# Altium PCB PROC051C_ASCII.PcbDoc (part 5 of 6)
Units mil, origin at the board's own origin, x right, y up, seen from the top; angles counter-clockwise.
Board outline 3304.03 x 2647.77 mil, 6 copper layers (TOP, L2, L3, L4, L5, BOTTOM), stack 55.54 mil thick; 370 components, 273 nets, 1273 pads, 1381 vias.
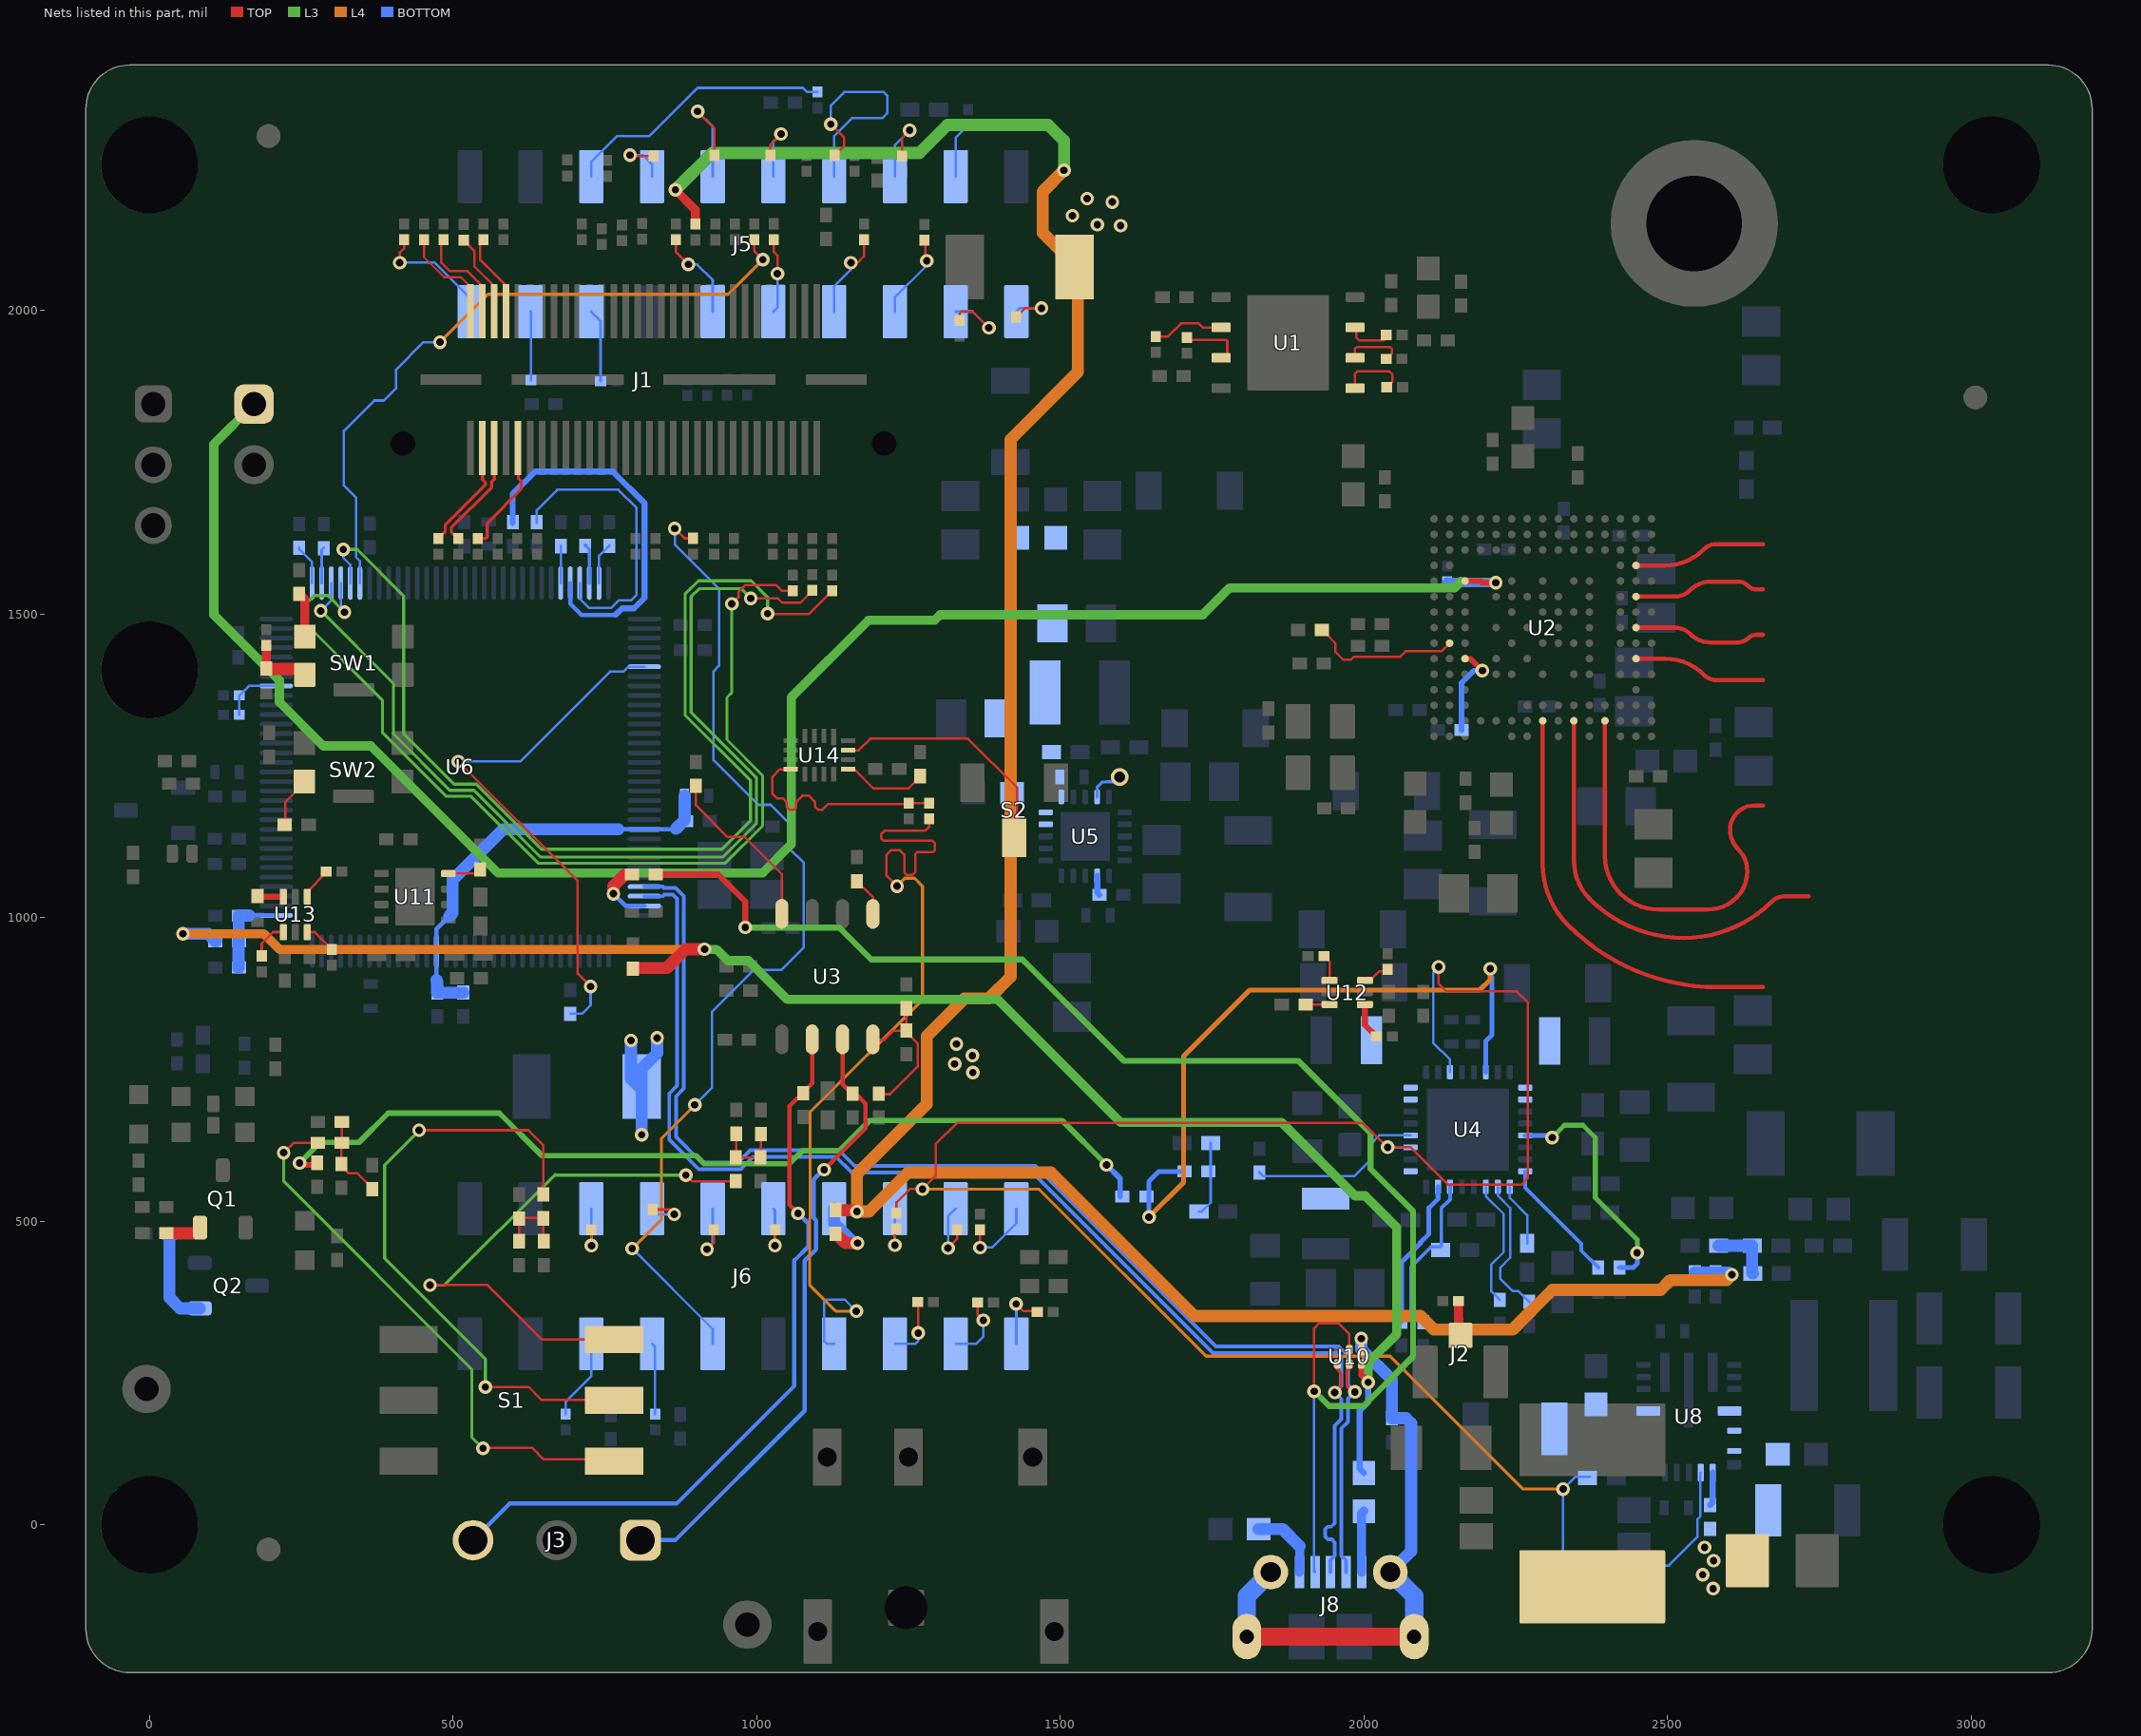
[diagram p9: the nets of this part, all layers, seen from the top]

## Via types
v1: diameter 22.4, hole 12.2, TOP to BOTTOM, tented both sides, 811 vias
v2: diameter 15.74, hole 5.9, TOP to L2, tented both sides, 528 vias
v3: diameter 19.68, hole 7.87, TOP to BOTTOM, 23 vias
v4: diameter 19.68, hole 7.87, TOP to BOTTOM, tented both sides, 7 vias
v5: diameter 22.4, hole 12.1, TOP to BOTTOM, tented both sides, 7 vias
v6: diameter 16, hole 8, TOP to BOTTOM, tented both sides, 4 vias
v7: diameter 15.74, hole 5.9, TOP to L2, tented top, 1 vias

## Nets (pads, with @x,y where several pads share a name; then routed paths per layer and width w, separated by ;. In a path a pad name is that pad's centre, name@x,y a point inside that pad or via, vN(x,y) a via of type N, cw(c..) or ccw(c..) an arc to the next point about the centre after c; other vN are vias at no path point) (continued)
NetJ1_52: J1.52 R50.1 | length 187.2
  TOP w5.2: R50.1@540.75,1624.71 553.36,1624.71 556,1627.35 556,1649.94 611.8,1705.74 611.8,1719.71 607.36,1724.15 J1.52@607.36,1773.27
NetJ1_53: J1.53 R22.2 | length 137.5
  TOP w4: R22.2@550.11,2116.73 544.7,2111.32 544.7,2083.31 587.67,2040.34 J1.53@587.67,1999.25
NetJ1_55: J1.55 R33.2 | length 138
  TOP w4: R33.2@517.39,2116.29 535,2098.68 535,2073 567.99,2040.01 J1.55@567.99,1999.25
NetJ1_56: J1.56 R49.1 | length 182.6
  TOP w5.2: R49.1@508.25,1624.71 497.03,1635.93 497.03,1642.53 563.2,1708.7 563.2,1717.88 567.99,1722.67 J1.56@567.99,1773.27
NetJ1_57: J1.57 R21.2 | length 164.6
  TOP w4: R21.2@484.35,2116.73 480,2112.38 480,2080.01 495.01,2065 524,2065 548.3,2040.7 J1.57@548.3,1999.25
NetJ1_58: J1.58 R48.1 | length 182.6
  TOP w5.2: R48.1@475.61,1624.71 486.83,1635.93 486.83,1646.76 553,1712.93 553,1717.35 548.3,1722.05 J1.58@548.3,1773.27
NetJ1_59: J1.59 R20.2 | length 165.6
  TOP w4: R20.2@452.11,2116.73 452.11,2087.89 485,2055 513.01,2055 528.62,2039.39 J1.59@528.62,1999.25
NetJ2_1: J2.1 R111.2 | length 58.2
  TOP w15: R111.2@2155.99,369 2155.99,340.01 2156,315.04 J2.1@2159,312.04
NetJ3_1: J3.1 R85.2 U3.7 | length 1034
  TOP w7: v1(1111,585) 1179.1,653.1 1179.1,693.8 1163.2,709.7 1158,709.7 1157,709.7 1141.31,725.39 U3.7@1141.31,798.65
  BOTTOM w7: J3.1@808.4,-25.28 865.72,-25.28 1079,188 1079,435 1097.7,453.7 1097.7,501.68 1094,505.38 1094,569 1110,585 v1(1111,585)
NetJ3_3: J3.3 R87.1 U3.6 | length 1242
  TOP w7: v1(1068,513) 1054,527 1054,690 1075.89,711.89 1091.31,727.31 U3.6@1091.31,798.65
  BOTTOM w7: J3.3@532.8,-25.28 593.08,35 868,35 1062,229 1062,435.71 1085,458.71 1085,496 v1(1068,513)
NetJ5_1: J5.1 R19.2 | length 203
  TOP w4: v1(412,2079) 412,2095 419.25,2102.25 R19.2@419.25,2116.73
  BOTTOM w4: v1(412,2079) 469.5,2079 527.5,2021 J5.1@527.5,1998.28
NetJ5_3: J5.3 R24.2 | length 112.9
  BOTTOM w4: J5.3@627.5,1998.28 628.11,1997.67 R24.2@628.11,1885.6
NetJ5_5: J5.5 R25.2 | length 120.8
  BOTTOM w4: J5.5@727.5,1998.28 742.81,1982.97 R25.2@742.81,1883.8
NetJ5_6: J5.6 R1.1 | length 449.8
  BOTTOM w4: J5.6@727.5,2220.72 727.5,2244.5 770.5,2287.5 823.1,2287.5 902.5,2366.9 1076,2366.9 1082.91,2359.99 R1.1@1100,2359.99
NetJ5_8: J5.8 R9.1 | length 102
  TOP w4: v1(791.2,2256.2) 792.69,2254.71 R9.1@829.75,2254.71
  BOTTOM w4: v1(791.2,2256.2) 812.2,2256.2 827.5,2240.9 J5.8@827.5,2220.72
NetJ5_9: J5.9 R26.2 | length 152.1
  TOP w4: R26.2@866.7,2116.61 866.7,2096.7 v1(887.4,2076)
  BOTTOM w4: v1(887.4,2076) 902,2076 927.5,2050.5 J5.9@927.5,1998.28
NetJ5_10: J5.10 R2.1 | length 201.2
  TOP w4: v1(902.66,2328) 930.05,2300.61 R2.1@930.05,2255.71
  BOTTOM w4: v1(902.66,2328) 927.5,2303.16 J5.10@927.5,2220.72
NetJ5_11: J5.11 R18.2 | length 124
  TOP w4: R18.2@1028.21,2117.08 1028.21,2096.79 1034.1,2090.9 v1(1034.1,2061)
  BOTTOM w4: J5.11@1027.5,1998.28 1034.1,2004.88 v1(1034.1,2061)
NetJ5_12: J5.12 R4.1 | length 118
  TOP w4: R4.1@1022.55,2255.71 1022.55,2273.55 v1(1040,2291)
  BOTTOM w4: J5.12@1027.5,2220.72 1027.5,2278.5 v1(1040,2291)
NetJ5_13: J5.13 R31.2 | length 145.3
  TOP w4: v1(1155,2079) 1166,2079 1176.75,2089.75 R31.2@1176.75,2116.73
  BOTTOM w4: J5.13@1127.5,1998.28 1127.5,2040.5 1155,2068 v1(1155,2079)
NetJ5_14: J5.14 R6.1 | length 401.4
  TOP w4: v1(1122,2307) 1144,2285 1144,2271.66 R6.1@1128.05,2255.71
  BOTTOM w4: v1(1122,2307) 1122,2338 1144,2360 1209,2360 1215,2354 1215,2325 1207,2317 1157,2317 1127.5,2287.5 J5.14@1127.5,2220.72
NetJ5_15: J5.15 R32.2 | length 141.2
  TOP w4: R32.2@1277.55,2116.73 1278,2116.28 1278,2116.01 1278,2084 v1(1280,2082)
  BOTTOM w4: J5.15@1227.5,1998.28 1227.5,2021.5 1280,2074 v1(1280,2082)
NetJ5_16: J5.16 R10.1 | length 134
  TOP w4: R10.1@1239.25,2254.71 1239.25,2284.25 v1(1252,2297)
  BOTTOM w4: J5.16@1227.5,2220.72 1227.5,2272.5 v1(1252,2297)
NetJ5_17: J5.17 R35.2 | length 137.7
  TOP w4: R35.2@1334,1983.99 1334,1995 1337.5,1998.5 1355.59,1998.5 v1(1382.33,1971.76)
  BOTTOM w4: J5.17@1327.5,1998.28 1355.81,1998.28 v1(1382.33,1971.76)
NetJ5_18: J5.18 R8.1 | length 92.8
  BOTTOM w4: J5.18@1327.5,2220.72 1327.5,2284.51 R8.1@1348,2305.01
NetJ5_19: J5.19 R36.2 | length 91.5
  TOP w4: R36.2@1427.25,1989.71 1441.54,2004 v1(1469,2004)
  BOTTOM w4: J5.19@1427.5,1998.28 1433.22,2004 v1(1469,2004)
NetJ6_5: J6.5 R169.2 | length 133.6
  BOTTOM w4: R169.2@685.13,182.27 685.13,202.33 727.5,244.7 J6.5@727.5,298.28
NetJ6_6: J6.6 R104.1 | length 87.1
  TOP w4: v1(727.75,460) R104.1@727.75,486.29
  BOTTOM w4: J6.6@727.5,520.72 727.5,460.25 v1(727.75,460)
NetJ6_7: J6.7 R166.2 | length 118.2
  BOTTOM w4: J6.7@827.5,298.28 832.75,293.03 R166.2@832.75,182.27
NetJ6_8: J6.8 R94.1 | length 79.3
  TOP w4: R94.1@828.25,519.29 856.21,519.29 v1(864,511.5)
  BOTTOM w4: J6.8@827.5,520.72 836.72,511.5 v1(864,511.5)
NetJ6_9: J6.9 R165.2 | length 1685.6
  TOP w4: v1(865,1641) 881.01,1624.99 R165.2@895,1624.99
  L4 w5: v1(795,455) 843.13,503.13 843.13,636.71 897.9,691.48 v1(897.9,691.7)
  BOTTOM w4: v1(795,455) 927.5,322.5 J6.9@927.5,298.28 ; v1(865,1641) 865,1615 938,1542 938,1415 928.8,1405.8 928.8,1259.48 1002.28,1186 1023,1186 1056,1153 1056,1111.72 1065.52,1102.2 1065.95,1102.2 1077.5,1090.66 1077.5,951.5 1040,914 995,914 926,845 926,719.8 v1(897.9,691.7)
NetJ6_10: J6.10 R105.1 | length 108
  TOP w4: v1(918,453.9) 929.75,465.65 R105.1@929.75,486.29
  BOTTOM w4: v1(918,453.9) 927.5,463.4 J6.10@927.5,520.72
NetJ6_12: J6.12 R106.1 | length 88.1
  TOP w4: v1(1030,460) 1030.25,460.25 R106.1@1030.25,486.29
  BOTTOM w4: J6.12@1027.5,520.72 1030,518.22 v1(1030,460)
NetJ6_13: J6.13 R76.2 | length 1443.2
  TOP w4: v1(1231,1052) 1213.64,1069.36 1213.64,1103.64 1221,1111 1236.1,1111 1243,1104.1 1243,1075.1 1247.6,1070.5 1256.1,1070.5 1261.5,1075.9 1261.5,1105 1265,1108.5 1290.5,1108.5 1293,1111 1293,1123 1288.87,1127.13 1208.6,1127.13 1204.6,1131.13 1204.6,1137.29 1210.44,1143.13 1277.13,1143.13 1284,1150 R76.2@1284,1163.01
  L4 w5: v1(1164,352) 1130,352 1087.3,394.7 1087.3,504.44 1087.7,504.84 1087.7,679.7 1273,865 1273,1052 1260,1065 1244,1065 v1(1231,1052)
  BOTTOM w4: J6.13@1127.5,298.28 1115,298.28 1111,302.28 1111,367 1115,371 1145,371 v1(1164,352)
NetJ6_14: J6.14 R107.1 | length 119.2
  TOP w20: R107.1@1129.75,480.38 1130.14,479.99 1146.13,464 v1(1166,464)
  BOTTOM w20: J6.14@1127.5,520.72 1127.5,496.5 1160,464 v1(1166,464)
NetJ6_15: J6.15 R164.2 | length 104.9
  TOP w4: R164.2@1265.01,367 1266,366.01 v1(1266,316)
  BOTTOM w4: J6.15@1227.5,298.28 1261.28,298.28 1266,303 v1(1266,316)
NetJ6_16: J6.16 R102.1 | length 88.1
  TOP w4: v1(1227.5,460.5) 1227.5,484.54 R102.1@1230.25,487.29
  BOTTOM w4: v1(1227.5,460.5) J6.16@1227.5,520.72
NetJ6_17: J6.17 R163.2 | length 110.2
  TOP w4: R163.2@1364.01,366 1364.02,345.98 v1(1373,337)
  BOTTOM w4: J6.17@1327.5,298.28 1361.44,298.28 1373,309.84 v1(1373,337)
NetJ6_18: J6.18 R108.1 | length 106.3
  TOP w4: v1(1315,456) 1330.35,471.35 R108.1@1330.35,486.09
  BOTTOM w4: v1(1315,456) 1315,508.22 J6.18@1327.5,520.72
NetJ6_19: J6.19 R162.2 | length 107.6
  TOP w4: v1(1427,364) 1439,352 1458.01,352 1459.51,353.5 R162.2@1462.01,356
  BOTTOM w4: v1(1427,364) 1427.5,363.5 J6.19@1427.5,298.28
NetJ6_20: J6.20 R109.1 | length 129.5
  TOP w4: v1(1367.85,456.8) R109.1@1367.85,486.09
  BOTTOM w4: v1(1367.85,456.8) 1387.61,456.8 1427.5,496.69 J6.20@1427.5,520.72
NetJ8_1: J8.1 R161.1 | length 101.9
  BOTTOM w15: J8.1@1996.18,-77.86 1996.18,18.68 R161.1@2000,22.5
NetJ8_5: J8.5 R175.2 | length 122
  BOTTOM w15: J8.5@1893.82,-77.86 1894,-77.68 1894,-35
  BOTTOM w20: R175.2@1826.5,-7 1866,-7 1894,-35
NetJ8_6: J8.6 J8.9 J8.10 J8.11 R174.2 U10.1 | length 987.2
  TOP w10: U10.1@1995.69,287.59 v1(1995.69,307)
  TOP w30: J8.9@1807.2,-184.16 J8.6@2082.8,-184.16
  BOTTOM w20: v1(1995.69,307) 1995.69,289.31 2046,239 R174.2@2046,175.69 2069.31,175.69 2078,167 2078,-43.29 J8.11@2043.43,-77.86
  BOTTOM w30: J8.9@1807.2,-184.16 1807.2,-117.23 J8.10@1846.57,-77.86 ; J8.11@2043.43,-77.86 2082.8,-117.23 J8.6@2082.8,-184.16
NetL2_1: L2.1 U4.25 U4.26
NetL3_1: L3.1 U4.15 U4.16
NetL4_2: L4.2 U4.9
NetQ1_1: Q1.1 R116.2 | length 67.6
  TOP w20: R116.2@26.68,480.33 R116.2@27.47,480.33 83.18,480.33 Q1.1@83.18,489.51 Q1.1@83.18,491.47
NetQ2_1: Q2.1 R160.2 | length 163.1
  BOTTOM w20: R160.2@32.69,480 32.69,374.31 50.4,356.6 Q2.1@82.76,356.6
NetR3_1: R3.1 U12.3 | length 40.2
  TOP w4: R3.1@1903.2,857.1 1903.31,857.21 1903.99,857.21 U12.3@1943.37,857.22
NetR5_2: R5.2 U12.1 | length 44.3
  TOP w4: R5.2@1933.99,937 1943.37,927.63 U12.1@1943.37,896.59
NetR11_2: R11.2 U3.1 | length 64.9
  TOP w4: R11.2@1165,1060.31 1191.31,1034 U3.1@1191.31,1006.33
NetR12_2: R12.2 U3.4 | length 285.1
  TOP w4: R12.2@900,1217.31 900,1185 952,1133 980.31,1133 1041.31,1072 U3.4@1041.31,1007.31
NetR39_2: R39.2 U1.2 | length 119.7
  TOP w4: R39.2@1656.9,1957.49 1677.49,1957.49 1699,1979 1727.76,1979 1734.58,1972.18 U1.2@1764.89,1972.18
NetR40_1: R40.1 U1.7 | length 69.4
  TOP w4: U1.7@1987.33,1972.18 1987.33,1955.67 1992,1951 2032.84,1951 R40.1@2036.69,1954.85
NetR42_2: R42.2 U1.3 | length 107.1
  TOP w4: R42.2@1708.5,1955.79 1712.29,1952 1773,1952 1775,1950 1775,1925 1772.18,1922.18 U1.3@1764.89,1922.18 U1.3@1762.93,1922.18
NetR44_1: R44.1 U1.6 | length 98.7
  TOP w4: U1.6@1985.37,1922.18 1985.37,1937.37 1988,1940 2043,1940 2046,1937 2046,1929.66 R44.1@2036.69,1920.35
NetR45_1: R45.1 U1.5 | length 114.4
  TOP w4: U1.5@1985.37,1872.18 1985.37,1896.37 1989,1900 2042,1900 2047,1895 2047,1883.16 R45.1@2037.69,1873.85
NetR47_1: R47.1 U2.G14 | length 247.1
  TOP w4: R47.1@1931.68,1469 1936,1469 1953,1452 1953,1437.78 1965.66,1425.11 1978.67,1425.11 1983.56,1430 2060,1430 2069.02,1439.02 2127.72,1439.02 U2.G14@2141.01,1452.31
NetR68_1: R68.1 SW1.4 | length 69.3
  TOP w15: R68.1@246.04,1534.25 246.43,1533.86 255.94,1524.35 SW1.4@255.94,1469.02
NetR72_1: R72.1 R73.2 SW1.2 | length 104.1
  TOP w15: R73.2@192.05,1409.82 192.44,1410.21 192.5,1410.27 192.5,1410.61 R72.1@192.5,1448.26
  TOP w20: R73.2@192.05,1409.82 252.14,1409.82 SW1.2@255.94,1406.02
NetR79_2: R79.2 SW2.2 | length 90.4
  TOP w4: R79.2@223.35,1153.14 223.35,1190.35 252.04,1219.04 252.04,1224.5 252.04,1227.45 SW2.2@254.99,1230.4
NetR81_1: R81.1 U2.F13 | length 157
  TOP w9: U2.F13@2166.6,1426.72 2175.28,1426.72 v1(2195,1407)
  BOTTOM w9: R81.1@2160.68,1309 2160.68,1386.68 2181,1407 v1(2195,1407)
NetR82_2: R82.2 U8.18 | length 55.3
  BOTTOM w10: R82.2@2570,32.69 2574.37,37.06 U8.18@2574.37,86.19
NetR86_1: R86.1 R177.2 R178.1 U3.8 | length 248.6
  TOP w4: U3.8@1191.31,798.65 1210.11,798.65 1225.06,813.6 R86.1@1246.3,813.6 ; R178.1@1200.8,709.5 1219.7,709.5 1265,754.8 1265,793 1246.3,811.7 R86.1@1246.3,813.6 ; R177.2@1246.5,851.45 R177.2@1246.5,850.66 1246.5,832 1246.3,831.8 R86.1@1246.3,814.39 R86.1@1246.3,813.6
NetR88_2: R88.2 R89.2 R92.1 R93.1 | length 120.8
  TOP w4: R88.2@966.12,644.95 R88.2@966.12,644.16 966.12,605.53 966.12,605.25 966.01,605.14 965.62,604.75 1005.82,604.75 1006.21,605.14 R93.1@1006.58,605.51 ; R93.1@1006.58,605.53 R89.2@1006.58,643.86 R89.2@1006.58,644.65
NetR92_2: R92.2 S1.3 | length 924.1
  TOP w4: v1(462,395) 556.29,395 646.29,305 S1.3@765.29,305 ; v1(883.4,576) 893.23,566.16 R92.2@965.62,566.16
  L3 w5: v1(462,395) 486,395 668,577 669,576 v1(883.4,576)
NetR95_1: R95.1 R96.2 R112.1 R113.2 | length 118.5
  TOP w4: R113.2@608.92,466.45 608.78,466.59 608.78,467.24 R96.2@608.78,504.56 608.78,505.35 648.52,505.35 648.82,505.65 R95.1@648.82,504.86 648.82,467.24 648.82,466.95 648.93,466.84 R112.1@649.32,466.45
NetR95_2: R95.2 S1.2 | length 1056.1
  TOP w4: v1(444,650) 624,650 648.82,625.18 R95.2@648.82,544.24 ; v1(553,227) 624.29,227 645.29,206 743.88,206 743.88,205 743.88,191.88 765.29,191.88 766.51,191.88 S1.2@772.46,197.83
  L3 w5: v1(444,650) 444,649.64 387.08,592.72 387.08,438.92 553,273 v1(553,227)
NetR98_2: R98.2 R99.1 R101.1 R114.2 | length 137.8
  TOP w4: R114.2@316.69,662 R99.1@316.68,629 316,628.32 R98.2@316,594.69 316,591 328,579 342.53,579 R101.1@367.28,554.25
NetR99_2: R99.2 S1.1 | length 911.6
  TOP w4: v1(221,613) 237,629 R99.2@277.31,629 ; v1(549,126) 550,127 630,127 649,108 762.29,108 S1.1@765.29,105
  L3 w5: v1(221,613) 221,566 530.72,256.28 530.72,144.28 v1(549,126)
NetR119_2: R119.2 U4.2 | length 232.5
  BOTTOM w4: U4.2@2222.2,555.06 U4.2@2220.48,556.78 2220.48,542.52 2241,522 2241,440.03 2224.3,423.33 2224.3,405.7 2244.6,385.4 2253.97,385.4 R119.2@2272,367.37
NetR120_2: R120.2 U5.12 | length 32.6
  BOTTOM w10: U5.12@1560.72,1069.04 1560.68,1041.63 R120.2@1564.31,1038
NetR121_2: R121.2 U4.3 | length 212.3
  BOTTOM w4: U4.3@2200.8,556.78 2200.8,541.2 2230,512 2230,449 2210,429 2210,384.69 R121.2@2224,370.69
NetR123_1: R123.1 U6.63 | length 69.2
  BOTTOM w4: U6.63@740.14,1551.19 740.14,1596.11 756.89,1612.86 R123.1@757.28,1613.25
NetR124_1: R124.1 U6.61 | length 488.4
  BOTTOM w4: R124.1@637.72,1650.75 R124.1@637.72,1651.53 637.72,1671.22 671.5,1705 772,1705 802,1675 802,1532 792.8,1522.8 772.8,1522.8 760.5,1510.5 723.5,1510.5 709,1525 709,1550.83 U6.61@708.64,1551.19
NetR125_2: R125.2 U6.59 | length 61.9
  BOTTOM w4: U6.59@677.14,1551.19 677.14,1612.16 677.14,1612.57 R125.2@677.52,1612.95
NetR126_1: R126.1 U6.62 | length 64.8
  BOTTOM w6: R126.1@717.68,1613.25 718.07,1612.86 724.39,1606.54 U6.62@724.39,1551.19
NetR127_1: R127.1 U6.60 | length 632.6
  BOTTOM w7: U6.60@692.89,1551.19 692.89,1517.05 710.94,1499 767.38,1499
  BOTTOM w10: R127.1@598.12,1650.75 R127.1@598.12,1651.53 598.12,1698.11 635.01,1735 763,1735 815,1683 815,1526.62 798.18,1509.8 778.18,1509.8 767.38,1499
NetR128_2: R128.2 U6.33 | length 67.5
  BOTTOM w4: R128.2@246.5,1609.95 R128.2@246.5,1609.16 246.5,1606.98 267.7,1585.78 U6.33@267.7,1551.19
NetR129_2: R129.2 U6.34 | length 59.9
  BOTTOM w4: U6.34@283.44,1551.19 283.44,1606.04 286.61,1609.21 R129.2@287,1609.6
NetR135_2: R135.2 R136.2 U6.25 | length 99.4
  BOTTOM w4: R136.2@147.77,1334.29 R135.2@147.77,1366.19 163.58,1382 208.54,1382 U6.25@208.64,1381.9
NetR139_2: R139.2 R146.1 R157.2 | length 101.5
  BOTTOM w20: R146.1@2584.24,460 R157.2@2639.38,460 2639.38,415 R139.2@2640.38,414
NetR142_1: R142.1 R149.1 U4.6 | length 266.5
  BOTTOM w6: R149.1@2098,333.68 2078,353.68 2078,425 2111,458 2125.54,458 2127.38,459.83 2127.38,521.38 2142,536 2142,556.52 U4.6@2141.74,556.78
NetR143_2: R143.2 U4.29 | length 396.8
  L3 w8: v1(2310,638) 2330.22,658.2 2360.79,658.2 2381.02,637.97 2381.02,538.98 2450,470 v1(2450,448.12)
  BOTTOM w8: U4.29@2265.76,641.43 v1@2306.57,641.43 ; R143.2@2421,423.69 2443.83,423.69 2450,429.86 v1(2450,448.12)
NetR144_2: R144.2 U4.12 | length 294.7
  BOTTOM w4: R144.2@1828,580.31 1834.17,574.15 1984.15,574.15 2012.68,602.68 2012.68,629.11 2025,641.43 U4.12@2076.78,641.43
NetR148_1: R148.1 U4.7 | length 247
  BOTTOM w8: R148.1@2062,334.68 2062,432.67 2093.12,463.79 2093.12,465.12 2107,479 2107,522 2122.06,537.06 U4.7@2122.06,556.78
NetR152_1: R152.1 U6.95 | length 111.1
  TOP w20: v1(764,1039.5) 764,1052.41 783.09,1071.5 R152.1@794.32,1071.5 R152.1@795.1,1071.5
  BOTTOM w7: v1(764,1039.5) 783.81,1019.69 U6.95@814.94,1019.69
NetR155_1: R155.1 U6.70 | length 902.2
  TOP w4: v1(508.4,1257.3) 705,1060.7 705,908.2 v1(726.4,886.8)
  BOTTOM w4: v1(508.4,1257.3) 610.3,1257.3 758.3,1405.3 780.49,1405.3 788.58,1413.39 U6.70@814.94,1413.39 ; R155.1@692.78,842.25 712.74,842.25 726.4,855.91 v1(726.4,886.8)
NetR158_1: R158.1 U4.1 | length 105.1
  BOTTOM w4: U4.1@2240.17,556.78 2240.17,538.83 2269,510 R158.1@2269,463.62
NetR159_2: R159.2 U4.32 | length 208.5
  BOTTOM w6: U4.32@2265.76,582.37 2265.76,555.24 2358,463 2358,451.69 R159.2@2386,423.69
NetR167_2: R167.2 U12.4 | length 60.5
  TOP w10: U12.4@2001.63,857.22 2001.63,823.58 R167.2@2020.61,804.6
NetR168_1: R168.1 U12.6 | length 45
  TOP w4: U12.6@2001.63,896.59 2010.02,896.59 2025.33,911.9 2035.89,911.9 R168.1@2039,915.01
NetR186_1: R186.1 R189.1 R190.2 | length 123.7
  BOTTOM w4: R186.1@1728.38,516 1733,516 1747.62,530.62 1747.62,582 R190.2@1747.62,629
NetR188_1: R188.1 R189.2 U4.22 | length 1159.7
  L4 w8: v1(1646,507) 1703,564 1703,772 1811.8,880.8 2190.57,880.8 2208,898.23 v1(2208,916)
  BOTTOM w8: v1(1646,507) 1645.62,507.38 1645.62,541 1645.62,565.62 1662,582 R189.2@1700.38,582 ; U4.22@2200.8,745.76 2200.8,796.8 2211,807 2211,902 2208,905 v1(2208,916)
NetR194_2: R194.2 U11.8 | length 48.9
  TOP w4: U11.8@495.96,1072.89 544.7,1072.89 R194.2@544.9,1072.89
NetR197_1: R197.1 U13.3 | length 42.8
  TOP w10: R197.1@177.8,1035.3 178.57,1034.53 U13.3@220.32,1034.53
NetR198_2: R198.2 U13.1 | length 54.1
  TOP w4: U13.1@259.69,1034.53 259.69,1043.08 290.61,1074 R198.2@290.61,1075.8
NetR199_1: R199.1 U13.6 | length 52.4
  TOP w4: U13.6@259.69,976.27 271.82,976.27 R199.1@300.3,947.79
NetR201_1: R201.1 U13.4 | length 63.7
  TOP w4: R201.1@184.9,937.19 184.9,957.9 203.27,976.27 U13.4@220.32,976.27
NetR208_1: R208.1 U14.13 | length 140.9
  TOP w4: U14.13@1150.24,1244.38 1160.95,1244.38 1192.28,1213.05 1250.05,1213.05 1269,1232 R208.1@1269,1233.32
NetS2_2: S2.2 U14.15 | length 402.7
  TOP w4: U14.15@1150.24,1275.87 1167.87,1275.87 1187,1295 1348,1295 1428.9,1214.1 1428.9,1131.72 S2.2@1428.9,1131.45
NetTP2_1: TP2.1 U5.4 | length 60.3
  BOTTOM w5: U5.4@1560.72,1198.96 1560.72,1215.27 1569.25,1223.8 1576.54,1223.8 1576.65,1223.91 1590.02,1223.91 TP2.1@1597.88,1231.78
PGOOD: R27.1 R107.2 R138.2 R141.2 | length 4452.9
  TOP w15: v1(866,2199) 898.8,2166.2 R27.1@898.8,2142.49
  TOP w20: R107.2@1129.75,518.18 1159.86,518.18 1162.04,516 v1(1165,516)
  L3 w20: v1(866,2199) 926.8,2259.8 1267.8,2259.8 1314,2306 1480,2306 1506,2280 v1(1506,2231)
  L4 w20: v1(1506,2231) 1471,2196 1471,2128 1529,2070 1529,1899 1418,1788 1418,902.53 1382.47,867 1342,867 1280,805 1280,693 1165,578 v1(1165,516) 1185,516 1249.2,580.2 1484.8,580.2 1721,344 2093,344 2115.2,321.8 2244.84,321.8 2310.3,387.27 2488.8,387.27 2504.73,403.2 2597.2,403.2 v1(2606,412)
  BOTTOM w20: R138.2@2545,415.69 R141.2@2579,415.69 2600.5,415.69 2604.18,412 v1(2606,412)
PMIC_CLK: R97.2 R188.2 | length 1547.6
  TOP w9: v1(247,596) 250.16,592.84 R97.2@275,592.84
  L3 w9: v1(247,596) 281,630 345,630 393,678 576,678 646,608 900,608 913,595 1054,595 1075,616 1136,616 1186,666 1503,666 v1(1576,593)
  BOTTOM w9: v1(1576,593) 1598.38,570.62 R188.2@1598.38,541
PMIC_EN1: R84.1 R102.2 U4.11 U4.19 U8.19 | length 3669.3
  TOP w4: R102.2@1230.25,513.27 1230.25,531.25 1252,553 v1(1273,553) 1294.81,574.81 1294.81,627.05 1329.76,662 1998,662 2038.5,621.5 2039,621 v1(2039,622) 2077.05,622 2138.74,560.31 2259.03,560.31 2270.14,571.43 2270.14,860.16 2251.69,878.61 2135.55,878.61 2123,891.16 v1(2123,919)
  L4 w5: v1(1273,553) 1465,553 1740,278 2043,278 2262,59 v1(2328,59)
  BOTTOM w4: v1@2040,621 2040.74,621.74 U4.11@2076.78,621.74 ; v1(2123,919) 2114,910 2114,794 2141.74,766.26 U4.19@2141.74,745.76 ; R84.1@2372.31,79 2368.38,79 2348,79 v1(2328,59) 2328,-48.6 2346.4,-67 2502,-67 2549,-20 2549,9 2554.16,14.16 2554.16,85.66 U8.19@2554.68,86.19
RX1: U2.M2 | length 312.8
  TOP w7.08: U2.M2@2448.09,1580.26 2496.4,1580.26 ; 2657.22,1615.6 2581.07,1615.6 ; 2496.4,1580.26 ccw(c2496.4,1669.28) 2559.79,1606.78 ; 2496.4,1580.26 ccw(c2496.4,1669.28) 2559.79,1606.78 ; 2559.79,1606.79 cw(c2581.07,1585.5) 2581.07,1615.6 ; 2559.79,1606.79 cw(c2581.07,1585.5) 2581.07,1615.6
RX2: U2.K2 | length 318.3
  TOP w7.08: U2.K2@2448.09,1529.08 2512.28,1529.08 ; 2656.92,1540.8 2646.47,1540.8 ; 2512.28,1529.08 ccw(c2512.28,1563.6) 2536.69,1539.19 ; 2512.28,1529.08 ccw(c2512.28,1563.6) 2536.69,1539.19 ; 2536.7,1539.19 cw(c2571.24,1504.66) 2571.24,1553.5 ; 2536.7,1539.19 cw(c2571.24,1504.66) 2571.24,1553.5 ; 2571.24,1553.5 2615.82,1553.5 ; 2615.82,1553.5 cw(c2615.82,1528.95) 2633.18,1546.31 ; 2615.82,1553.5 cw(c2615.82,1528.95) 2633.18,1546.31 ; 2633.19,1546.3 ccw(c2646.47,1559.58) 2646.47,1540.8 ; 2633.19,1546.3 ccw(c2646.47,1559.58) 2646.47,1540.8
RX3: U2.H2 | length 318.3
  TOP w7.08: U2.H2@2448.09,1477.9 2512.28,1477.9 ; 2656.92,1466.18 2646.47,1466.18 ; 2512.28,1477.9 cw(c2512.28,1443.38) 2536.69,1467.79 ; 2512.28,1477.9 cw(c2512.28,1443.38) 2536.69,1467.79 ; 2536.7,1467.79 ccw(c2571.24,1502.32) 2571.24,1453.48 ; 2536.7,1467.79 ccw(c2571.24,1502.32) 2571.24,1453.48 ; 2571.24,1453.48 2615.82,1453.48 ; 2615.82,1453.48 ccw(c2615.82,1478.03) 2633.18,1460.67 cw(c2615.82,1478.03) 2615.82,1453.48 ; 2646.47,1466.18 ccw(c2646.47,1447.4) 2633.19,1460.68 cw(c2646.47,1447.4) 2646.47,1466.18
RX4: U2.F2 | length 313.6
  TOP w7.08: U2.F2@2448.09,1426.72 2496.4,1426.72 ; 2657.4,1391.2 2581.51,1391.2 ; 2496.4,1426.72 cw(c2496.4,1337.7) 2559.79,1400.2 ; 2496.4,1426.72 cw(c2496.4,1337.7) 2559.79,1400.2 ; 2559.79,1400.19 ccw(c2581.5,1421.91) 2581.5,1391.2 ; 2559.79,1400.19 ccw(c2581.5,1421.91) 2581.5,1391.2
SPICLK1: R75.1 R76.1 U14.8 | length 370
  TOP w4: U14.8@1055.76,1244.38 1038.02,1244.38 1026,1232.36 1026,1204 1033.2,1196.8 1043.2,1196.8 1049,1191 1049,1183 1054,1178 1061,1178 1065,1182 1065,1190.8 1075.2,1201 1086,1201 1096,1191 1096,1183 1101,1178 1108,1178 1117,1187 1248.01,1187 R75.1@1250,1188.99 R76.1@1284,1188.99
TX1: U2.B4 | length 1074.1
  TOP w7.08: U2.B4@2396.91,1324.36 2396.91,1102.05 ; 2657.3,1184.9 2642.61,1184.9 ; 2396.91,1102.05 ccw(c2485.46,1102.05) 2485.46,1013.5 ; 2396.91,1102.05 ccw(c2485.46,1102.05) 2485.46,1013.5 ; 2485.46,1013.5 2566.65,1013.5 ; 2566.65,1013.5 ccw(c2566.65,1079.79) 2613.53,1032.92 cw(c2566.65,1079.79) 2566.65,1013.5 ; 2603.07,1144.8 cw(c2643.55,1144.8) 2614.93,1173.43 ; 2603.07,1144.78 ccw(c2647.37,1144.78) 2616.04,1113.46 ; 2603.07,1144.8 cw(c2643.55,1144.8) 2614.93,1173.43 ; 2603.07,1144.78 ccw(c2647.37,1144.78) 2616.04,1113.46 ; 2614.94,1173.43 cw(c2642.62,1145.76) 2642.61,1184.9 ; 2614.94,1173.43 cw(c2642.62,1145.76) 2642.61,1184.9 ; 2616.05,1113.46 cw(c2578.8,1076.22) 2631.47,1076.22 ; 2616.05,1113.46 cw(c2578.8,1076.22) 2631.47,1076.22 ; 2631.47,1076.22 cw(c2570.24,1076.22) 2613.54,1032.93 ccw(c2570.24,1076.22) 2631.47,1076.22
TX2: U2.B6 | length 1122.2
  TOP w7.08: U2.B6@2345.73,1324.36 2345.73,1094.33 ; 2732.11,1035.3 2692.06,1035.3 ; 2345.73,1094.33 ccw(c2435.71,1094.33) 2372.08,1030.71 ; 2345.73,1094.33 ccw(c2435.71,1094.33) 2372.08,1030.71 ; 2372.11,1030.68 ccw(c2526.5,1185.06) 2526.5,966.73 ; 2372.11,1030.68 ccw(c2526.5,1185.06) 2526.5,966.73 ; 2526.5,966.73 ccw(c2526.5,1172.53) 2672,1026.99 ; 2526.5,966.73 ccw(c2526.5,1172.53) 2672,1026.99 ; 2672.01,1026.99 cw(c2692.07,1006.94) 2692.06,1035.3 ; 2672.01,1026.99 cw(c2692.07,1006.94) 2692.06,1035.3
TX3: U2.B8 | length 1082.1
  TOP w7.08: U2.B8@2294.55,1324.36 2294.34,1324.15 2294.34,1089.06 ; 2657.3,885.68 2582.22,885.68 ; 2294.34,1089.06 ccw(c2437.96,1089.06) 2336.4,987.51 ; 2294.34,1089.06 ccw(c2437.96,1089.06) 2336.4,987.51 ; 2336.41,987.5 ccw(c2582.22,1233.3) 2582.22,885.68 ; 2336.41,987.5 ccw(c2582.22,1233.3) 2582.22,885.68
VBUS_1_DETECT: C69.2 R151.1 R153.2 U6.1 | length 147.8
  BOTTOM w7: 163.95,1003.95 U6.1@208.64,1003.95
  BOTTOM w20: R153.2@146.55,917.74 146.55,961.04 146.94,961.43 146.95,1003.56 C69.2@147.34,1003.56 163.56,1003.56 163.95,1003.95
VCC_LDO_OUT: C44.1 C72.1 C95.1 C96.1 L8.1 L9.1 R83.2 R122.2 U5.1 U5.19 U5.20
VDDC_1: C62.1 C64.2 C74.2 C75.2 U6.87 U6.115 | length 697.8
  BOTTOM w7: 472.42,897.18 U6.115@472.42,944.89 472.42,981.42 493.6,1002.6 ; 771.82,1145.68 U6.87@814.94,1145.68 861.38,1145.68
  BOTTOM w20: 472.42,897.18 472.7,896.9 472.7,895.48 473.68,894.5 C75.2@473.68,876.84 473.68,876.45 C74.2@516.6,876.45 ; 493.6,1002.6 499,1008 499,1062.4 582.28,1145.68 771.82,1145.68 ; 866.81,1146.5 881.31,1161 C62.1@881.31,1201
VIN: C21.1 C23.1 C25.1 C26.1 C27.1 L7.2 R34.2 R82.1 R115.2 U8.4 U8.14 U8.15 U8.16 | length 257.4
  BOTTOM w20: v1(793,798) 793,734.55 808.05,719.5 R115.2@810.55,717 ; v1(810.55,642.45) R115.2@810.55,717 ; v1@836,801 836,777 810.55,751.55 R115.2@810.55,722 R115.2@810.55,717
  other v1: 2575,-105 2558,-82 2576,-59 2561,-37 1356,745 1326,759 1355,773 1329,792 836,802 1599.3,2140 1561,2141.5 1520,2156.5 1585.7,2178.9 1544,2184.5
VPP_1P7: C8.1 P7.1 U2.L13 | length 3156.7
  TOP w10: U2.L13@2166.6,1554.67 2191.27,1554.67 2194.09,1551.85 2194.24,1552 v1(2217,1552)
  L3 w10: 2159.8,1553.8 2215.2,1553.8 v1(2217,1552)
  L3 w15: P7.1@171.94,1846.15 105.82,1780.03 105.82,1499.09 213.8,1391.11 213.8,1355.42 286.12,1283.1 364.47,1283.1 573.87,1073.7 1009.7,1073.7 1056.9,1120.9 1056.9,1362.9 1184,1490 1293.23,1490 1302.23,1499 1734.36,1499 1778.36,1543 2149,1543 2159.8,1553.8
  BOTTOM w15: C8.1@2137,1553.01 2137.7,1552.3 2211.23,1552.3 2211.93,1553 2216,1553 v1(2217,1552)
XDSET_1_D_N: J8.2 U6.93 U10.5 | length 2172.5
  TOP w5.2: U10.5@1976,264.95 1976,256.44 1972.13,252.57 1972.13,228.91 1979.78,221.26 v1@1984,221.26
  BOTTOM w6: U6.93@814.94,1051.19 845.1,1051.19 847.07,1049.22 866.36,1049.22 880,1035.57 880,719 867,706 867,639 909,597 969,597 989.21,617.21 1135.21,617.21 1161.11,591.31 1458.82,591.31 1756.13,294 1958.56,294 1973.6,278.96 1973.6,230.4 v1(1985,219) 1973.58,207.58 1973.58,169.58 1962.9,158.9 1962.9,-50.9 1970.59,-58.59 J8.2@1970.59,-77.86
XDSET_1_D_P: J8.3 U6.94 U10.4 | length 2173.2
  TOP w5.2: v1@1952.28,219.26 1961.93,228.91 1961.93,250.83 1956.32,256.44 U10.4@1956.32,264.95
  BOTTOM w6: U6.94@814.94,1035.44 845.1,1035.44 847.87,1038.22 861.8,1038.22 869,1031.02 869,723.56 856,710.56 856,634.44 904.44,586 973.56,586 993.77,606.21 1130.66,606.21 1156.55,580.31 1454.26,580.31 1751.57,283 1954,283 1962.6,274.4 1962.6,228.6 v1(1952,218) 1962.58,207.42 1962.58,174.14 1951.9,163.45 1951.9,2.9 1946,-3 1940,-3 1936,-7 1936,-19 1941,-24 1947,-24 1951.9,-28.9 1951.9,-51.1 1945,-58 J8.3@1945,-77.86
XDSET_1_ID: J8.4 R152.2 U10.2 | length 2480.3
  TOP w4: v1(1918,220) 1918,324 1926.2,332.2 1957.8,332.2 1976,314 U10.2@1976,288.57
  TOP w10: R152.2@832.9,1071.5 R152.2@833.69,1071.5 936.5,1071.5 981,1027 v1(981,984)
  L3 w10: v1(981,984) 1136,984 1188.5,931.5 1437.5,931.5 1604.8,764.2 1892.18,764.2 2011,645.38 2011,586.37 2081,516.37 2081,277.6 1999.2,195.8 1942.8,195.8 1918.6,220 v1(1918,220)
  BOTTOM w4: v1(1918,220) 1918,-76.45 J8.4@1919.41,-77.86
XDSET_1_VBUS: R151.2 R154.2 R161.2 U10.6 | length 2858
  TOP w10: U10.6@1995.69,264.95 1995.69,247.31 2007,236 v1(2007,235)
  TOP w20: R154.2@796,916.31 796,917.1 851.9,917.1 882.8,948 v1(914,948)
  L3 w15: v1(914,948) 933.64,948 952.34,929.3 986.49,929.3 1050.49,865.3 1396.7,865.3 1599,663 1864.35,663 1985.35,542 2002,542 2053.7,490.3 2053.7,313.7 2007,267 v1(2007,235)
  L4 w15: v1(55,973.5) 188.5,973.5 214,948 v1(914,948) v1@915,948
  BOTTOM w10: R161.2@2000,85.5 1993,92.5 1993,188 2007.2,202.2 2007.2,234.8 v1(2007,235)
  BOTTOM w20: v1(55,973.5) 96.29,973.5 108.36,961.43 R151.2@108.75,961.04
XDSET_TCK: R70.2 U6.35 | length 1651.3
  TOP w4: v1(990,1526) 1035,1526 1042,1519 1072,1519 1091.33,1538.33 R70.2@1091.33,1538.73
  L3 w5: v1(282,1505.5) 401.6,1385.9 401.6,1303 494.6,1210 534,1210 644,1100 944.14,1100 999.7,1155.56 999.7,1230.3 892,1338 892,1528.9 905.1,1542 975,1542 990,1527 v1(990,1526)
  BOTTOM w4: v1(282,1505.5) 299.19,1522.69 U6.35@299.19,1551.19
XDSET_TDI: R30.2 U6.38 | length 1125.2
  TOP w4: R30.2@995.75,2116.73 995.75,2098.25 v1(1010,2084)
  L4 w5: v1(478.2,1948) 557.2,2027 953,2027 v1(1010,2084)
  BOTTOM w4: U6.38@346.44,1551.19 346.44,1587.68 340,1594.12 340,1692 320,1712 320,1802 370,1852 386,1852 406,1872 406,1902.8 451.2,1948 v1(478.2,1948)
XDSET_TDO: R71.2 U6.37 | length 1812.2
  TOP w4: v1(1018,1501) 1018,1500 1085.6,1500 R71.2@1124.33,1538.73
  L3 w5: v1(319,1606.5) 342.1,1606.5 418.4,1530.2 418.4,1303.2 501.6,1220 538.2,1220 645.3,1112.9 942.9,1112.9 989.7,1159.7 989.7,1226.16 882,1333.86 882,1533.04 903.96,1555 990.86,1555 1018,1527.86 v1(1018,1501)
  BOTTOM w4: v1(319,1606.5) 319,1593.3 330.69,1581.61 U6.37@330.69,1551.19
XDSET_TMS: R69.2 U6.36 | length 1651.1
  TOP w4: v1(959,1517) 969.8,1527.8 969.8,1536.8 981.2,1548.2 1031.53,1548.2 1041,1538.73 R69.2@1059.25,1538.73
  L3 w5: v1(321,1503.5) 293.9,1530.6 271.6,1530.6 256.9,1515.9 256.9,1485 383.5,1358.4 383.5,1305.3 488.8,1200 529.8,1200 639.8,1090 948.28,1090 1009.7,1151.42 1009.7,1234.44 950.94,1293.2 950.94,1362.81 959,1370.86 v1(959,1517)
  BOTTOM w4: U6.36@314.94,1551.19 314.94,1509.56 v1(321,1503.5)
pads on no net: D2.1@37.49,1105.47 D2.2@69.97,1105.47 FID1.1 FID2.1 FID3.1 FID4.1 FID5.1 FID6.1 J1.20 J1.22 J1.32 J1.34 J1.35 J1.37 J1.38 J1.39 J1.40 J1.41 J1.43 J1.45 J1.47 J1.49 J1.MH1 J1.MH2 J5.7 J5.20 J6.3 J6.11 J8.7 J8.8 LBL1.0 P6.MH1 SW1.1 SW1.3 SW2.1 SW2.3 U1. U4. U6.2 U6.3 U6.4 U6.5 U6.6 U6.11 U6.12 U6.13 U6.14 U6.15 U6.18 U6.19 U6.20 U6.21 U6.22 U6.23 U6.24 U6.27 U6.29 U6.30 U6.31 U6.32 U6.41 U6.42 U6.43 U6.44 U6.45 U6.46 U6.49 U6.50 U6.53 U6.54 U6.56 U6.57 U6.65 U6.67 U6.71 U6.72 U6.73 U6.74 U6.75 U6.76 U6.77 U6.78 U6.81 U6.82 U6.83 U6.84 U6.85 U6.86 U6.91 U6.92 U6.97 U6.98 U6.99 U6.100 U6.102 U6.103 U6.104 U6.105 U6.106 U6.107 U6.108 U6.109 U6.110 U6.111 U6.112 U6.116 U6.117 U6.118 U6.119 U6.120 U6.121 U6.123 U6.124 U6.125 U6.126 U6.127 U6.128 U7.3 U8.4A U8.4B U8.8A U8.8B U8.9A U8.9B U8.9C U8.9D U8.10A U8.10B U8.14A U8.14B U11.7 U11.9@436.9,1009.7 U11.9@436.9,1059.3 U14.9 U14.12

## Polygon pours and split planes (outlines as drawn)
no net on Top Solder (solid, pour order 766): 1740.13,1910.38 1792.23,1910.38 1792.23,1933.98 1740.13,1933.98 1740.13,1910.38
no net on Top Solder (solid): 1958.03,1860.38 2010.13,1860.38 2010.13,1883.98 1958.03,1883.98 1958.03,1860.38
no net on Top Solder (solid): 1740.13,1860.38 1792.23,1860.38 1792.23,1883.98 1740.13,1883.98 1740.13,1860.38
no net on Top Solder (solid): 1740.13,1960.38 1792.23,1960.38 1792.23,1983.98 1740.13,1983.98 1740.13,1960.38
no net on Top Solder (solid): 1740.13,2010.38 1792.23,2010.38 1792.23,2033.98 1740.13,2033.98 1740.13,2010.38
no net on Top Solder (solid): 1958.03,1910.38 2010.13,1910.38 2010.13,1933.98 1958.03,1933.98 1958.03,1910.38
no net on Top Solder (solid): 1958.03,1960.38 2010.13,1960.38 2010.13,1983.98 1958.03,1983.98 1958.03,1960.38
no net on Top Solder (solid): 1958.03,2010.38 2010.13,2010.38 2010.13,2033.98 1958.03,2033.98 1958.03,2010.38
no net on Top Solder (solid): 1974,2174.42 2001.92,2146.5 2358,2146.5 2358,2324.5 1596,2324.5 1596,2219.87 1974,2219.87
no net on Top Solder (solid): 66 vertices, not listed, extent 2259,542.58 3179.92,1748.3
GND on TOP "Bottom Layer - L12-No Net" (solid, remove dead copper, pour order 1109): 49 vertices, not listed, extent 2207,-223.91 3182.62,2386.89
no net on TOP "Top Layer-No Net" (solid, pour order 1058): 2108.38,2181.95 2108.38,2187.85 2120.19,2187.85 2143.81,2188.44 2291.6,2188.44 2315.22,2187.85 2327.03,2187.85 2327.03,2181.95 2315.22,2181.95 2291.6,2181.36 2143.81,2181.36 2120.19,2181.95
no net on TOP "Top Layer-No Net" (solid, pour order 1057): 1631.53,2270.05 1643.34,2270.05 1666.96,2269.46 2292.4,2269.46 2316.02,2270.05 2327.83,2270.05 2327.83,2275.95 2316.02,2275.95 2292.4,2276.54 1666.96,2276.54 1643.34,2275.95 1631.53,2275.95
GND on TOP "TOP-GND 1" (solid, remove dead copper, pour order 1040): 2358,2324.5 2358,2146.5 1974,2146.5 1974,2219.5 1596,2219.5 1596,2324.5 2358,2324.5
NetC1_2 on TOP "TOP-UNNAMED_41_RESISTOR_I120_1" (solid, pour order 1091): 2010.13,2032.97 1958.03,2032.97 1958.03,2009.6 2010.13,2009.6
AR_VOUT_PA on TOP "TOP_AR_VOUT_PA_P1033" (solid, remove dead copper, pour order 1033): 28 vertices, not listed, extent 2435.66,1123.1 2537.04,1331.75
NetC79_1 on TOP "TOP_NETC79_1_P1061" (solid, remove dead copper, pour order 1061): 2153,165 2153,22 2159,16 2492,16 2512,36 2512,215 2499,228 2284,228 2238,182 2170,182
AR_1V8 on TOP "TOP_AR_1V8_P1060" (solid, remove dead copper, pour order 1060): 18 vertices, not listed, extent 2103,1003 2179.6,1159.35
GND on TOP "Top Layer-No Net" (solid, remove dead copper, pour order 1056): 1807,2027.5 1807,1868 1942,1868 1942,2027.5
GND on TOP "TOP-GND 11" (solid, pour order 1054): 146 vertices, not listed, extent 404.9,926.5 469.4,1143.5
GND on TOP "TOP-GND 10" (solid, remove dead copper, pour order 1053): 247 vertices, not listed, extent 85,1255 374.65,1390
GND on TOP "TOP-GND 7" (solid, pour order 1052): 162 vertices, not listed, extent 203.3,998.49 266.88,1020.8
GND on TOP "TOP-GND" (solid, pour order 1051): 1792.23,1883.98 1740.13,1883.98 1740.13,1860.38 1792.23,1860.38 1792.23,1883.98
AR_QSPI_CS on TOP "TOP-AR_QSPI_CS" (solid, pour order 1050): 1792.23,2033.98 1740.13,2033.98 1740.13,2010.38 1792.23,2010.38 1792.23,2033.98
NetR42_2 on TOP "TOP-UNNAMED_41_RESISTOR_I116_2" (solid, pour order 1049): 1792.23,1933.98 1740.13,1933.98 1740.13,1910.38 1792.23,1910.38 1792.23,1933.98
NetR44_1 on TOP "TOP-UNNAMED_41_RESISTOR_I117_1" (solid, pour order 1048): 2010.13,1933.98 1958.03,1933.98 1958.03,1910.38 2010.13,1910.38 2010.13,1933.98
NetR45_1 on TOP "TOP-UNNAMED_41_RESISTOR_I118_1" (solid, pour order 1047): 2010.13,1883.98 1958.03,1883.98 1958.03,1860.38 2010.13,1860.38 2010.13,1883.98
NetR39_2 on TOP "TOP-UNNAMED_41_RESISTOR_I119_2" (solid, pour order 1046): 1792.23,1983.98 1740.13,1983.98 1740.13,1960.38 1792.23,1960.38 1792.23,1983.98
NetR40_1 on TOP "TOP-UNNAMED_41_RESISTOR_I120_1" (solid, pour order 1045): 2010.13,1983.98 1958.03,1983.98 1958.03,1960.38 2010.13,1960.38 2010.13,1983.98
NetC85_1 on TOP "TOP-UNNAMED_7_CAPNONPOLARIZED_I5_2" (solid, pour order 1044): 194 vertices, not listed, extent 281.9,916.5 393.44,1055.5
RX1 on TOP "TOP-RX1" (solid, remove dead copper, pour order 1032): 34 vertices, not listed, extent 2653.04,1586.07 2946.35,1645.13
RX2 on TOP "TOP-RX2" (solid, remove dead copper, pour order 1031): 34 vertices, not listed, extent 2653.04,1511.27 2946.35,1570.32
RX3 on TOP "TOP-RX3" (solid, remove dead copper, pour order 1030): 34 vertices, not listed, extent 2653.04,1436.47 2946.35,1495.52
RX4 on TOP "TOP-RX4" (solid, remove dead copper, pour order 1029): 34 vertices, not listed, extent 2653.04,1361.66 2946.35,1420.72
TX1 on TOP "TOP-TX1" (solid, remove dead copper, pour order 1028): 34 vertices, not listed, extent 2653.04,1155.37 2946.35,1214.43
TX2 on TOP "TOP-TX2" (solid, remove dead copper, pour order 1027): 34 vertices, not listed, extent 2727.85,1005.77 3021.15,1064.82
TX3 on TOP "TOP-TX3" (solid, remove dead copper, pour order 1026): 34 vertices, not listed, extent 2653.04,856.16 2946.35,915.21
VIN on TOP "TOP_VIN_P1041" (solid, remove dead copper, pour order 1041): 1481,2019 1485,2015 1553,2015 1568,2030 1568,2063 1613,2108 1613,2183 1598,2198 1491,2198 1481,2188
NetJ1_1 on TOP "TOP-UNNAMED_43_QSH03001XD_I1_1" (solid, pour order 1038): 200 vertices, not listed, extent 1074.64,1728.5 1376.03,2133.5
AR_1V24 on TOP "TOP-PMIC_1V2" (solid, pour order 1037): 2040.38,1702 2100.39,1642 2027,1642.01 2020,1649 1901,1649 1880.01,1670 1879.96,1731.1 1990.47,1731.09 2019.57,1702
AR_3V3 on TOP "TOP-+3.3VD" (solid, pour order 1039): 46 vertices, not listed, extent 2199.7,1683.22 2279.99,1778.9
VIN on TOP "TOP_VIN_P1062" (solid, remove dead copper, pour order 1062): 2591,166.09 2591,35 2525,-31 2245,-31 2232,-44 2232,-154 2245,-167 2645,-167 2680,-132 2680,157.59 2657.14,180.44 2605.35,180.44
GND on TOP "TOP-GND 14" (solid, pour order 1055): 29 vertices, not listed, extent 2470.96,1643.56 2511.09,1679.7
GND on TOP "TOP-GND 3" (solid, pour order 1042): 34 vertices, not listed, extent 2653.04,1660.87 2946.35,1719.93
GND on TOP "TOP-GND 4" (solid, remove dead copper, pour order 1043): 34 vertices, not listed, extent 2653.04,1286.86 2946.35,1345.92
GND on TOP "TOP-GND 3" (solid, remove dead copper, pour order 1059): 2398.5,1993 2697.5,1993 2697.5,2295 2398.5,2295 2398.5,1993
NetF1_2 on TOP "TOP_NETF1_2_P1036" (solid, remove dead copper, pour order 1036): 1052,53 1138,-33 1639,-33 1719,47 2093,47 2109,63 2109,177 2095,191 1757,191 1692,256 1122.76,256 1052,185.24
VIN on L4 "L4_VIN_P1067" (solid, remove dead copper, pour order 1067): 19 vertices, not listed, extent 647,-158 2608,830
GND on L4 "L4-GND" (solid, pour order 1065): 555 vertices, not listed, extent 384.02,1961.83 938.88,2306.08
AR_1V8 on L4 "L4_AR_1V8_P1069" (solid, remove dead copper, pour order 1069): 2106.48,1071.9 2505.62,1071.9 2549,1115.28 2549,1516.14 2363.16,1702 2275,1702 2258,1685 2258,1562 2073.04,1377.04 2073.04,1105.34
NetC85_1 on L4 "L4-UNNAMED_7_CAPNONPOLARIZED_I5_2" (solid, pour order 1066): 96 vertices, not listed, extent 268.9,983.7 319.5,1073.6
GND on L4 "L4_GND_P1064" (solid, remove dead copper, pour order 1064): 2358,1406 2371.01,1393.01 2398,1393 2406,1385 2406,1352 2383,1329 2222,1329 2192,1359 2192,1484 2234.99,1526.99 2322,1527 2358,1491
VIN on L4 "L4_VIN_P1063" (solid, remove dead copper, pour order 1063): 18 vertices, not listed, extent 1308,682 1638,2197
3V3_REF on L4 "L4_3V3_REF_P1068" (solid, remove dead copper, pour order 1068): 1747,485.4 1773.34,459.06 2504.17,459.06 2614.61,351 2686.19,351 2786,450.81 2786,637.63 2554.62,869 1815,869 1747,801
GND on BOTTOM "BOTTOM_GND_P1105" (solid, remove dead copper, pour order 1105): 45 vertices, not listed, extent 1931.7,-227.24 3176.6,2396.08
GND on BOTTOM "BOTTOM_GND_P1089" (solid, remove dead copper, pour order 1089): 37 vertices, not listed, extent 2152,-224.76 2827.36,301
AR_3V3 on BOTTOM "BOTTOM_AR_3V3_P1104" (solid, pour order 1104): 2498.44,855.46 2517.94,874.95 2669.62,874.95 2676.49,868.08 2676.49,821.49 2674,819 2594.06,819.27 2579.96,805.17 2573.82,805.17 2567,798.35 2567,786.43 2556.91,776.34 2528.09,776.34 2496.42,808 2496.42,853.43
VCC_LDO_OUT on BOTTOM "BOTTOM_VCC_LDO_OUT_P1093" (solid, pour order 1093): 25 vertices, not listed, extent 1373,1148.03 1513,1645.72
GND on BOTTOM "BOTTOM_GND_P1094" (solid, pour order 1094): 2357.7,965.1 2355.98,966.82 2183.97,966.82 2131.09,1020.22 2023.76,1020.22 1964.82,961.23 1964.82,729.74 2357.7,729.74
AR_1V8 on BOTTOM "BOTTOM_AR_1V8_P1095" (solid, pour order 1095): 20 vertices, not listed, extent 2065.12,1082 2257.54,1239.99
GND on BOTTOM "BOTTOM_GND_P1096" (solid, pour order 1096): 1744.51,1416.01 1744.51,1163.62 1744.51,911.26 1738.03,917.74 1430.68,917.74 1364.56,983.86 1364.56,1097.68 1407.2,1140.32 1455.38,1140.32 1455.47,1344.11 1455.43,1547.9 1474.55,1567.06 1593.46,1567.06
3V3 on BOTTOM "BOTTOM_3V3_P1090" (solid, remove dead copper, pour order 1090): 2807,681.25 2807,595 2758,546 2758,506 2764,500 2813,500 2818,495 2818,398 2803,383 2803,179 2807,175 2954,175 2954,628 2900.75,681.25
GND on BOTTOM "BOTTOM_GND_P1088" (solid, remove dead copper, pour order 1088): 2620,206.28 2622.72,206.28 2691,138 2752,138 2752,151 2721,182 2688,182 2688,240.36 2663.91,264.45 2663.91,269.29 2638.91,294.29 2570.91,294.29 2564.91,288.29 2564.91,219.29 2577.91,206.28
NetC18_2 on BOTTOM "BOTTOM_NETC18_2_P1087" (solid, remove dead copper, pour order 1087): 19 vertices, not listed, extent 2515,158 2751,374
VIN on BOTTOM "BOTTOM_VIN_P1086" (solid, remove dead copper, pour order 1086): 40 vertices, not listed, extent 2256,-152 2703.01,221
3V3_REF on BOTTOM "BOTTOM_3V3_REF_P1085" (solid, remove dead copper, pour order 1085): 1896,493 1884,505 1884,520 1876,528 1820,528 1812,520 1812,429 1986,429 1992,435 1992,470 1969.01,493
NetL4_2 on BOTTOM "BOTTOM_NETL4_2_P1084" (solid, remove dead copper, pour order 1084): 2024,536 2015,536 1988,509 1903,509 1894,518 1894,557 1903.99,566.99 2005,567 2043.69,567 2064.47,587.78 2087.22,587.78 2091,584 2091,573.76 2053.23,536
AR_1P0_RF2 on BOTTOM "BOTTOM_AR_1P0_RF2_P1083" (solid, remove dead copper, pour order 1083): 45 vertices, not listed, extent 1301.9,1230 2778.87,2177.41
AR_1P0_RF1 on BOTTOM "BOTTOM_AR_1P0_RF1_P1082" (solid, remove dead copper, pour order 1082): 52 vertices, not listed, extent 1473.63,1446 2645.71,1986.51
AR_VOUT_PA on BOTTOM "BOTTOM_AR_VOUT_PA_P1081" (solid, remove dead copper, pour order 1081): 2441,1225.05 2430.5,1214.56 2430.5,1135.5 2434,1132 2527,1132 2547,1152 2547,1194 2530,1211 2502,1211 2489,1224 2489,1275 2478,1286 2448,1286 2441,1279
1V24 on BOTTOM "BOTTOM_1V24_P1079" (solid, remove dead copper, pour order 1079): 27 vertices, not listed, extent 1453,770.55 1950.29,1120.06
1V8 on BOTTOM "BOTTOM_1V8_P1078" (solid, remove dead copper, pour order 1078): 2173.8,1050.96 2170.84,1048 2170.84,1003.96 2172.88,1001.92 2288.32,1001.92 2289.77,999.52 2363.56,925.74 2363.43,755.57 2383,736 2428.56,736 2439.26,736 2460.67,757.4 2460.67,935.18 2344.88,1050.96
NetL2_1 on BOTTOM "BOTTOM_NETL2_1_P1077" (solid, remove dead copper, pour order 1077): 2254,723 2282.2,751.2 2282.2,846.2 2315.8,846.2 2326.5,835.5 2326.5,750.5 2270,694 2257,694 2254,697
NetL3_1 on BOTTOM "BOTTOM_NETL3_1_P1076" (solid, remove dead copper, pour order 1076): 2034,701 2042,693 2089,693 2089,705.52 2089,732 2039,782 2039,852 1990,852 1990,745 2026,709
3V3_REF on BOTTOM "BOTTOM_3V3_REF_P1075" (solid, remove dead copper, pour order 1075): 1893.52,756 1904.52,745 1971,745 2030,686 2087,686 2091,682 2091,659 2088.09,656.09 1775.91,656.08 1753,679 1753,745 1764,756
3V3_REF on BOTTOM "BOTTOM_3V3_REF_P1074" (solid, remove dead copper, pour order 1074): 18 vertices, not listed, extent 2254,573 2732,728
AR_1V8 on BOTTOM "BOTTOM_AR_1V8_P1073" (solid, remove dead copper, pour order 1073): 17 vertices, not listed, extent 2377.76,1378.19 2478.56,1445.21
MCU_5V on BOTTOM "BOTTOM_MCU_5V_P1072" (solid, remove dead copper, pour order 1072): 471,787 471,503 513,461 576,461 593,478 592,479 592,593 672,673 672,778 663,787
GND on BOTTOM "BOTTOM-AGND" (solid, pour order 1071): 2543,61 2543,67 2527,67 2527,51 2514,38 2514,9 2496,-9 2413,-9 2413,-58 2497,-58 2543,-12
NetC32_1 on BOTTOM "BOTTOM_NETC32_1_P1070" (solid, remove dead copper, pour order 1070): 2476,107 2476,8 2468,0 2415,0 2395,20 2395,94 2410,109 2474,109
AR_1V24 on BOTTOM "BOTTOM_AR_1V24_P1080" (solid, remove dead copper, pour order 1080): 41 vertices, not listed, extent 1743.58,1119.08 2390,1764
GND on BOTTOM "BOTTOM-No Net" (solid, pour order 1107): 1928.96,1242.96 1880,1194 1880,1132.9 1894.56,1118.35 1968.27,1118.35 1993.54,1143.61 1993.54,1240.05 1994.53,1241.05 1992.62,1242.96
GND on L3 "L3-GND 4" (solid, pour order 1098): 147 vertices, not listed, extent 128.34,1301 365.98,1529.24
GND on L3 "L3-GND" (solid, pour order 1097): 2405,2275 2675,2275 2675,2020 2495,2020 2405,2110 2405,2275
VIN on L3 "L3_VIN_P1092" (solid, remove dead copper, pour order 1092): 1342,810 1374.01,777.99 1374,691 1345,662 1136.8,662 1103.8,629 795,629 772,652 772,795 796,819 950,819 959,810
GND on L3 "L3_GND_P1099" (solid, remove dead copper, pour order 1099): 3156.74,-243.26 -87.75,-243.25 -116,-214.99 -116,2367 -75,2408 3157,2408 3199.26,2365.74 3199.26,-200.74
GND on L2 "L2-GND" (solid, pour order 1100): 2422,2264.5 2422,2017.5 2667,2017.5 2667,2264.5 2422,2264.5
GND on L2 "L2_GND_P1102" (solid, remove dead copper, pour order 1102): 3156.74,-243.26 -87.75,-243.25 -116,-214.99 -116,2367 -75,2408 3157,2408 3199.26,2365.74 3199.26,-200.74
no net on M6 Assembly Bottom (solid): 3048.2,1870.7 ccw(c3006.2,1870.7) 3006.2,1912.7 ccw(c3006.2,1870.7) 2964.2,1870.7 ccw(c3006.2,1870.7) 3006.2,1828.7 ccw(c3006.2,1870.7) 3048.2,1870.7
no net on M6 Assembly Bottom (solid): 238,-40.5 ccw(c196,-40.5) 196,1.5 ccw(c196,-40.5) 154,-40.5 ccw(c196,-40.5) 196,-82.5 ccw(c196,-40.5) 238,-40.5
no net on M6 Assembly Bottom (solid): 238,2287.5 ccw(c196,2287.5) 196,2329.5 ccw(c196,2287.5) 154,2287.5 ccw(c196,2287.5) 196,2245.5 ccw(c196,2287.5) 238,2287.5
no net on M5 Assembly Top (solid): 238,2287.5 ccw(c196,2287.5) 196,2329.5 ccw(c196,2287.5) 154,2287.5 ccw(c196,2287.5) 196,2245.5 ccw(c196,2287.5) 238,2287.5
